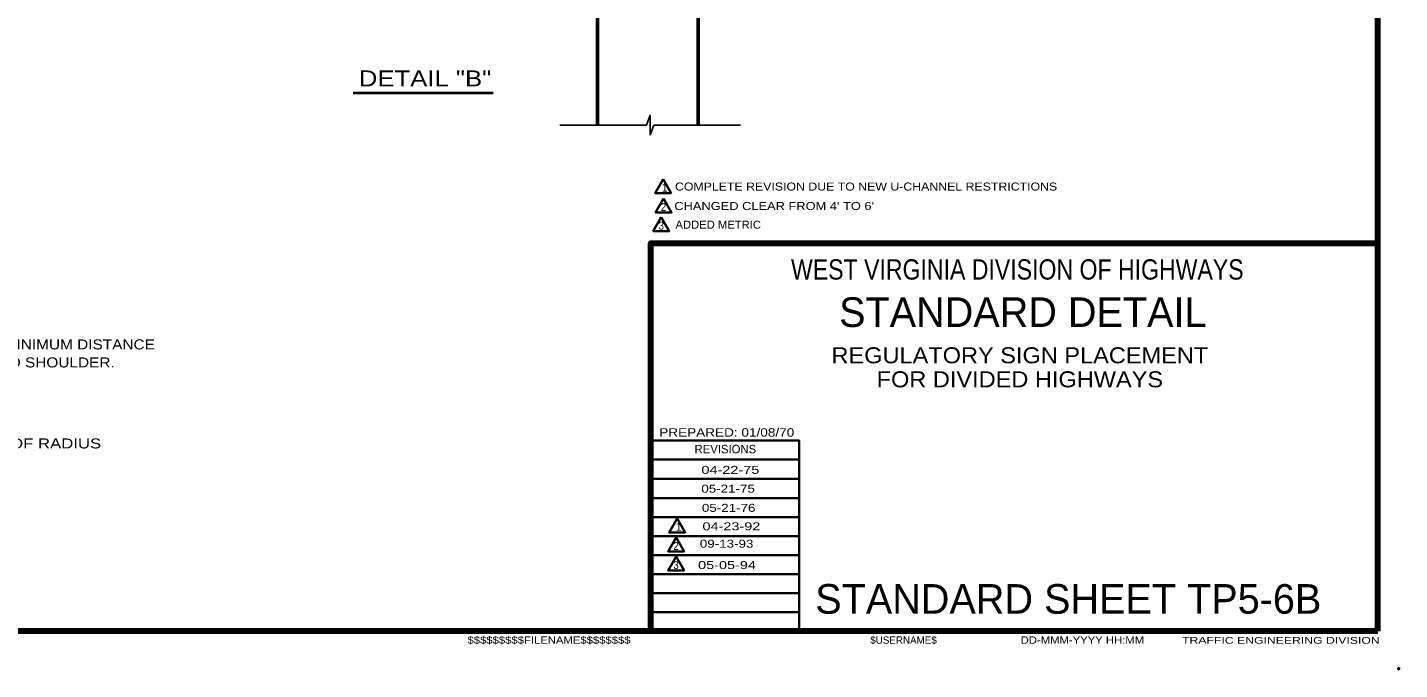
# Model space of a CAD drawing. Extents: x -198 to 658, y -402 to 142.
# Drawn here: x 246.2 to 657.8, y -402.2 to -209.7 of the extents above; entities that cross this region are included whole.
import ezdxf
from ezdxf.enums import TextEntityAlignment as Align

# ---------------------------------------------------------------- set-up
doc = ezdxf.new("R2010")
doc.units = 0
doc.header["$LTSCALE"] = 0.96
doc.header["$PDMODE"] = 32
doc.header["$PDSIZE"] = 0.48
doc.layers.add('1', color=7, linetype='Continuous', lineweight=35)
doc.layers.add('61', color=7, linetype='Continuous', lineweight=35)

msp = doc.modelspace()

# ---------------------------------------------------------------- linework, layer by layer
at = {"layer": '1', "lineweight": 158}
for q in [(651.2125, 135.4296), (651.2125, -274.3704), (-140.3875, -390.6704)]:
    msp.add_line((651.2125, -390.6704), q, dxfattribs=at)
at = {"layer": '1', "lineweight": 13}
msp.add_line((651.2125, -390.6704), (651.2125, 135.4296), dxfattribs=at)
at = {"layer": '1', "lineweight": 53}
for p, q in [((417.2472, -202.974), (417.2472, -238.974)), ((447.3947, -202.974), (447.3947, -238.974))]:
    msp.add_line(p, q, dxfattribs=at)
at = {"layer": '1', "lineweight": 40}
msp.add_line((343.9202, -229.2849), (385.8757, -229.2849), dxfattribs=at)
at = {"layer": '1', "lineweight": 25}
for p, q in [((405.9079, -238.9913), (431.8542, -238.9913)), ((434.1092, -238.9913), (432.9817, -241.9913)), ((434.1092, -238.9913), (460.0554, -238.9913))]:
    msp.add_line(p, q, dxfattribs=at)
at = {"layer": '1'}
for p, q in [((477.7125, -339.2704), (433.2125, -339.2704)), ((477.7125, -344.9704), (433.2125, -344.9704)), ((477.7125, -350.7704), (433.2125, -350.7704)), ((477.7125, -356.4704), (433.2125, -356.4704)), ((477.7125, -362.1704), (433.2125, -362.1704)), ((477.7125, -367.8704), (433.2125, -367.8704)), ((477.7125, -373.5704), (433.2125, -373.5704)), ((477.7125, -379.2704), (433.2125, -379.2704)), ((477.7125, -384.9704), (433.2125, -384.9704))]:
    msp.add_line(p, q, dxfattribs=at)
at = {"layer": '1', "lineweight": 25}
msp.add_lwpolyline([(432.9817, -241.9913), (432.9817, -235.9913), (431.8542, -238.9913)], dxfattribs=at)
at = {"layer": '1'}
for points in [[(436.8963, -255.1912), (434.4963, -259.3481), (439.2963, -259.3481)], [(437.022, -260.975), (434.622, -265.1319), (439.422, -265.1319)], [(436.3441, -266.5691), (433.9441, -270.726), (438.7441, -270.726)], [(441.0851, -356.9102), (438.6851, -361.0671), (443.4851, -361.0671)], [(440.7933, -362.6109), (438.3933, -366.7678), (443.1933, -366.7678)], [(440.7755, -368.339), (438.3755, -372.4959), (443.1755, -372.4959)]]:
    msp.add_lwpolyline(points, close=True, dxfattribs=at)
at = {"layer": '1', "lineweight": 158}
msp.add_lwpolyline([(433.2125, -390.6704), (433.2125, -274.3704), (651.2125, -274.3704)], dxfattribs=at)
at = {"layer": '1'}
msp.add_lwpolyline([(477.7125, -390.6704), (477.7125, -333.5704), (433.2125, -333.5704)], dxfattribs=at)
msp.add_point((657.5125, -401.9704), dxfattribs=at)
at = {"layer": '61', "lineweight": 53}
for q in [(498.5125, -390.6704), (498.5125, -390.6704), (498.5125, -390.6704), (498.8125, -390.6704), (498.8125, -390.6704)]:
    msp.add_line((651.2125, -390.6704), q, dxfattribs=at)

# ---------------------------------------------------------------- texts
at = {"layer": '1'}
for s, height, width, p in [('DETAIL "B"', 4.8, 1.2, (365.486, -227.3444)), ('COMPLETE REVISION DUE TO NEW U-CHANNEL RESTRICTIONS', 2.4, 1.15, (497.7604, -258.5712)), ('2', 2.4, 0.9, (436.9973, -264.6926)), ("CHANGED CLEAR FROM 4' TO 6'", 2.4, 1.2, (470.1874, -264.4074)), ('3', 2.4, 0.9, (436.3288, -270.2867)), ('ADDED METRIC', 2.4, 1.05, (453.4093, -270.0015)), ('WEST VIRGINIA DIVISION OF HIGHWAYS', 6.089, 0.85, (543.1125, -285.2704)), ('REGULATORY SIGN PLACEMENT', 4.8, 1.1, (543.8791, -310.374)), ('FOR DIVIDED HIGHWAYS', 4.8, 1.1, (543.879, -317.574)), ('- 15m FROM END OF RADIUS', 3, 1.25, (233.522, -335.9092)), ('2', 2.4, 0.9, (440.7686, -366.3285)), ('3', 2.4, 0.9, (440.7602, -372.0566))]:
    msp.add_text(s, height=height, dxfattribs=dict(at, width=width)).set_placement(p, align=Align.CENTER)
for s, height, p in [('1', 2.4, (437.3574, -258.8826)), ('STANDARD DETAIL', 8.881, (544.7625, -299.4704)), ('1', 2.4, (441.5462, -360.6016))]:
    msp.add_text(s, height=height, dxfattribs=at).set_placement(p, align=Align.CENTER)
for s, height, width, p in [('ALL SIGNS ARE 1.8m MINIMUM DISTANCE', 3, 1.15, (191.669, -306.2154)), ('FROM EDGE OF PAVED SHOULDER.', 3, 1.15, (191.669, -311.6154)), ('PREPARED: 01/08/70', 2.537, 1.2, (435.7125, -332.3704)), ('04-22-75', 2.4, 1.35, (448.3835, -343.5329)), ('05-21-75', 2.4, 1.25, (448.3499, -349.1784)), ('05-21-76', 2.4, 1.25, (448.507, -354.9223)), ('04-23-92', 2.4, 1.35, (448.6946, -360.4528)), ('09-13-93', 2.4, 1.25, (447.9006, -365.6722)), ('05-05-94', 2.4, 1.35, (447.3744, -372.0784)), ('$$$$$$$$$FILENAME$$$$$$$$', 2.2, 1.15, (378.2125, -394.4704)), ('DD-MMM-YYYY HH:MM', 2.2, 1.15, (544.1125, -394.4704)), ('TRAFFIC ENGINEERING DIVISION', 2.031, 1.35, (592.5125, -394.4704))]:
    msp.add_text(s, height=height, dxfattribs=dict(at, width=width)).set_placement(p)
for s, height, p in [('REVISIONS', 2.537, (446.3125, -337.3704)), ('STANDARD SHEET TP5-6B', 8.881, (482.5125, -385.4704)), ('$USERNAME$', 2.2, (499.0125, -394.4704))]:
    msp.add_text(s, height=height, dxfattribs=at).set_placement(p)

doc.saveas('drawing.dxf')
